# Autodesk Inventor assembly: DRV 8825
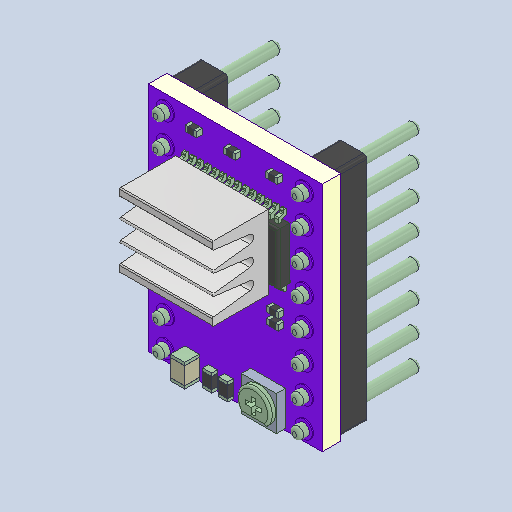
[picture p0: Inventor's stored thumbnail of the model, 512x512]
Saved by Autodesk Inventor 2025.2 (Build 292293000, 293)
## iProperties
Created: 2025-04
Part Number: DRV 8825
Description: PART--DESC
Document SubType Name: Assembly
Designer: BennF
Author: BennF
Revision Number: NONE
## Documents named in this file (9)
- C:\Users\BennF\Nextcloud\Benutzer\CNC JarBeRi\existing parts\Electronics\RepRap A4988 Shied (USE WITHOUT ARDUINO)\reprap-a4988-1.snapshot.1\RepRap\RepRap\DRV 8825_4.iam
- C:\Users\BennF\Nextcloud\Benutzer\CNC JarBeRi\existing parts\Electronics\RepRap A4988 Shied (USE WITHOUT ARDUINO)\reprap-a4988-1.snapshot.1\RepRap\RepRap\DRV 8825 Geometry.ipt
- C:\Users\BennF\Nextcloud\Benutzer\CNC JarBeRi\existing parts\Electronics\RepRap A4988 Shied (USE WITHOUT ARDUINO)\reprap-a4988-1.snapshot.1\RepRap\RepRap\PCB.ipt
- C:\Users\BennF\Nextcloud\Benutzer\CNC JarBeRi\existing parts\Electronics\RepRap A4988 Shied (USE WITHOUT ARDUINO)\reprap-a4988-1.snapshot.1\RepRap\RepRap\SMD Pot.ipt
- C:\Users\BennF\Nextcloud\Benutzer\CNC JarBeRi\existing parts\Electronics\RepRap A4988 Shied (USE WITHOUT ARDUINO)\reprap-a4988-1.snapshot.1\RepRap\RepRap\0603 Resistor.ipt
- C:\Users\BennF\Nextcloud\Benutzer\CNC JarBeRi\existing parts\Electronics\RepRap A4988 Shied (USE WITHOUT ARDUINO)\reprap-a4988-1.snapshot.1\RepRap\RepRap\0805 Capacitor.ipt
- C:\Users\BennF\Nextcloud\Benutzer\CNC JarBeRi\existing parts\Electronics\RepRap A4988 Shied (USE WITHOUT ARDUINO)\reprap-a4988-1.snapshot.1\RepRap\RepRap\0402 Resistor.ipt
- C:\Users\BennF\Nextcloud\Benutzer\CNC JarBeRi\existing parts\Electronics\RepRap A4988 Shied (USE WITHOUT ARDUINO)\reprap-a4988-1.snapshot.1\RepRap\RepRap\DRV8825 IC.ipt
- C:\Users\BennF\Nextcloud\Benutzer\CNC JarBeRi\existing parts\Electronics\RepRap A4988 Shied (USE WITHOUT ARDUINO)\reprap-a4988-1.snapshot.1\RepRap\RepRap\8 pin Header.ipt
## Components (16 placed, 8 different names)
1. DRV 8825 Geometry
2. PCB
3. SMD Pot
4. 0603 Resistor
5. 0603 Resistor:1
6. 0805 Capacitor
7. 0402 Resistor
8. 0402 Resistor:1
9. 0402 Resistor:2
10. 0402 Resistor:3
11. 0402 Resistor:4
12. 0402 Resistor:5
13. 0402 Resistor:6
14. DRV8825 IC
15. 8 pin Header
16. 8 pin Header:1
